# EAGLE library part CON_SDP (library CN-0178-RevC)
SDP Connector
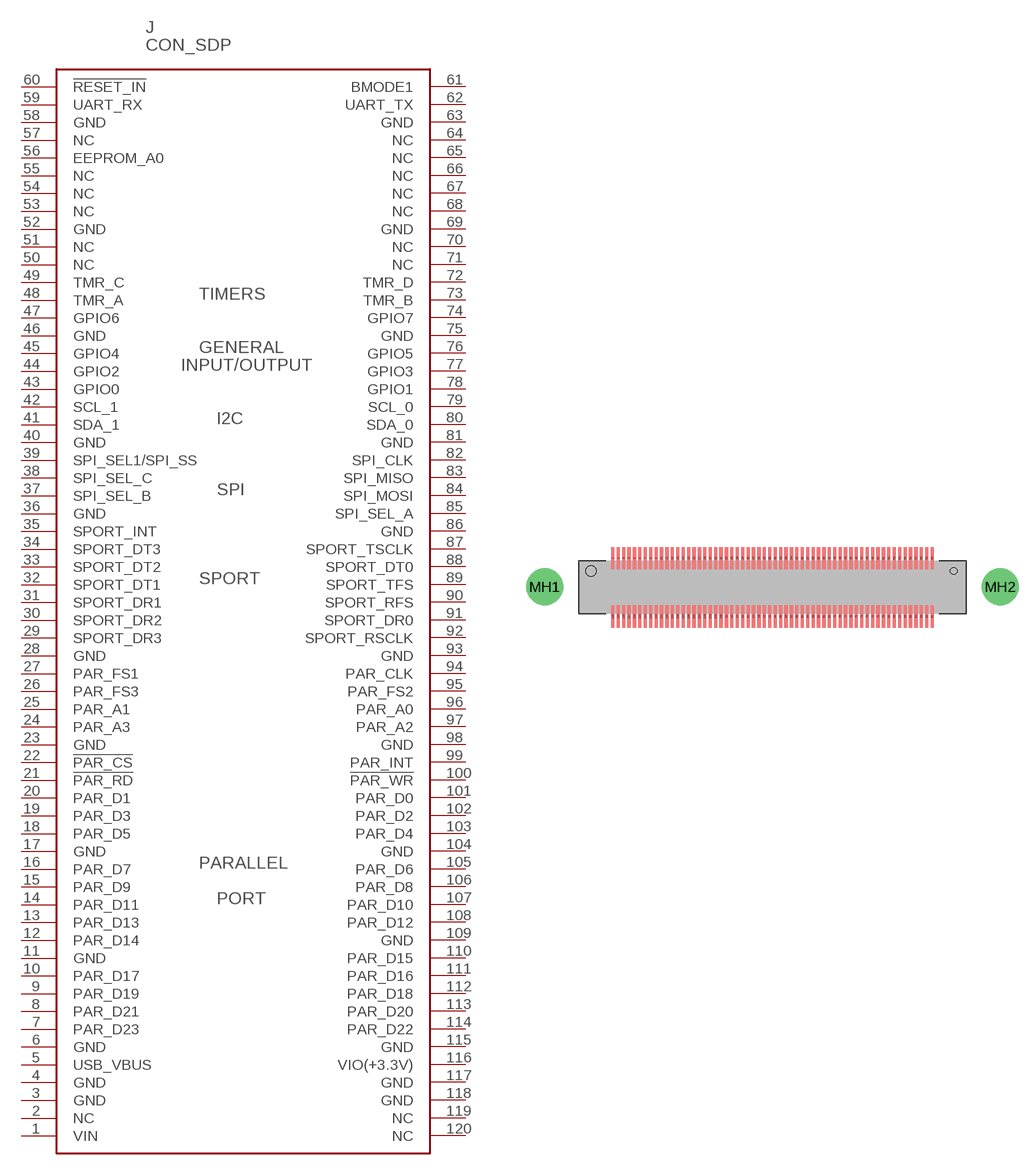
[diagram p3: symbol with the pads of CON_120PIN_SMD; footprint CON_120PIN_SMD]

Designator prefix J

## CON_SDP_120PIN_SMD  [CON_120PIN_SMD]
1  VIN  pas
2  NC  pas
3  GND  pas
4  GND  pas
5  USB_VBUS  pas
6  GND  pas
7  PAR_D23  pas
8  PAR_D21  pas
9  PAR_D19  pas
10  PAR_D17  pas
11  GND  pas
12  PAR_D14  pas
13  PAR_D13  pas
14  PAR_D11  pas
15  PAR_D9  pas
16  PAR_D7  pas
17  GND  pas
18  PAR_D5  pas
19  PAR_D3  pas
20  PAR_D1  pas
21  !PAR_RD  pas
22  !PAR_CS  pas
23  GND  pas
24  PAR_A3  pas
25  PAR_A1  pas
26  PAR_FS3  pas
27  PAR_FS1  pas
28  GND  pas
29  SPORT_DR3  pas
30  SPORT_DR2  pas
31  SPORT_DR1  pas
32  SPORT_DT1  pas
33  SPORT_DT2  pas
34  SPORT_DT3  pas
35  SPORT_INT  pas
36  GND  pas
37  SPI_SEL_B  pas
38  SPI_SEL_C  pas
39  SPI_SEL1/SPI_SS  pas
40  GND  pas
41  SDA_1  pas
42  SCL_1  pas
43  GPIO0  pas
44  GPIO2  pas
45  GPIO4  pas
46  GND  pas
47  GPIO6  pas
48  TMR_A  pas
49  TMR_C  pas
50  NC  pas
51  NC  pas
52  GND  pas
53  NC  pas
54  NC  pas
55  NC  pas
56  EEPROM_A0  pas
57  NC  pas
58  GND  pas
59  UART_RX  pas
60  !RESET_IN  pas
61  BMODE1  pas
62  UART_TX  pas
63  GND  pas
64  NC  pas
65  NC  pas
66  NC  pas
67  NC  pas
68  NC  pas
69  GND  pas
70  NC  pas
71  NC  pas
72  TMR_D  pas
73  TMR_B  pas
74  GPIO7  pas
75  GND  pas
76  GPIO5  pas
77  GPIO3  pas
78  GPIO1  pas
79  SCL_0  pas
80  SDA_0  pas
81  GND  pas
82  SPI_CLK  pas
83  SPI_MISO  pas
84  SPI_MOSI  pas
85  SPI_SEL_A  pas
86  GND  pas
87  SPORT_TSCLK  pas
88  SPORT_DT0  pas
89  SPORT_TFS  pas
90  SPORT_RFS  pas
91  SPORT_DR0  pas
92  SPORT_RSCLK  pas
93  GND  pas
94  PAR_CLK  pas
95  PAR_FS2  pas
96  PAR_A0  pas
97  PAR_A2  pas
98  GND  pas
99  PAR_INT  pas
100  !PAR_WR  pas
101  PAR_D0  pas
102  PAR_D2  pas
103  PAR_D4  pas
104  GND  pas
105  PAR_D6  pas
106  PAR_D8  pas
107  PAR_D10  pas
108  PAR_D12  pas
109  GND  pas
110  PAR_D15  pas
111  PAR_D16  pas
112  PAR_D18  pas
113  PAR_D20  pas
114  PAR_D22  pas
115  GND  pas
116  VIO(+3.3V)  pas
117  GND  pas
118  GND  pas
119  NC  pas
120  NC  pas

## Footprint CON_120PIN_SMD (pad centres in mm)
Hirose FX8-120s-SV(21), 120-pin receptacle, FEC 132-4660
smd 0.35 x 2.46: 1 -17.7,3.23; 2 -17.1,3.23; 3 -16.5,3.23; 4 -15.9,3.23; 5 -15.3,3.23; 6 -14.7,3.23; 7 -14.1,3.23; 8 -13.5,3.23; 9 -12.9,3.23; 10 -12.3,3.23; 11 -11.7,3.23; 12 -11.1,3.23; 13 -10.5,3.23; 14 -9.9,3.23; 15 -9.3,3.23; 16 -8.7,3.23; 17 -8.1,3.23; 18 -7.5,3.23; 19 -6.9,3.23; 20 -6.3,3.23; 21 -5.7,3.23; 22 -5.1,3.23; 23 -4.5,3.23; 24 -3.9,3.23; 25 -3.3,3.23; 26 -2.7,3.23; 27 -2.1,3.23; 28 -1.5,3.23; 29 -0.9,3.23; 30 -0.3,3.23; 31 0.3,3.23; 32 0.9,3.23; 33 1.5,3.23; 34 2.1,3.23; 35 2.7,3.23; 36 3.3,3.23; 37 3.9,3.23; 38 4.5,3.23; 39 5.1,3.23; 40 5.7,3.23; 41 6.3,3.23; 42 6.9,3.23; 43 7.5,3.23; 44 8.1,3.23; 45 8.7,3.23; 46 9.3,3.23; 47 9.9,3.23; 48 10.5,3.23; 49 11.1,3.23; 50 11.7,3.23; 51 12.3,3.23; 52 12.9,3.23; 53 13.5,3.23; 54 14.1,3.23; 55 14.7,3.23; 56 15.3,3.23; 57 15.9,3.23; 58 16.5,3.23; 59 17.1,3.23; 60 17.7,3.23; 61 17.7,-3.23; 62 17.1,-3.23; 63 16.5,-3.23; 64 15.9,-3.23; 65 15.3,-3.23; 66 14.7,-3.23; 67 14.1,-3.23; 68 13.5,-3.23; 69 12.9,-3.23; 70 12.3,-3.23; 71 11.7,-3.23; 72 11.1,-3.23; 73 10.5,-3.23; 74 9.9,-3.23; 75 9.3,-3.23; 76 8.7,-3.23; 77 8.1,-3.23; 78 7.5,-3.23; 79 6.9,-3.23; 80 6.3,-3.23; 81 5.7,-3.23; 82 5.1,-3.23; 83 4.5,-3.23; 84 3.9,-3.23; 85 3.3,-3.23; 86 2.7,-3.23; 87 2.1,-3.23; 88 1.5,-3.23; 89 0.9,-3.23; 90 0.3,-3.23; 91 -0.3,-3.23; 92 -0.9,-3.23; 93 -1.5,-3.23; 94 -2.1,-3.23; 95 -2.7,-3.23; 96 -3.3,-3.23; 97 -3.9,-3.23; 98 -4.5,-3.23; 99 -5.1,-3.23; 100 -5.7,-3.23; 101 -6.3,-3.23; 102 -6.9,-3.23; 103 -7.5,-3.23; 104 -8.1,-3.23; 105 -8.7,-3.23; 106 -9.3,-3.23; 107 -9.9,-3.23; 108 -10.5,-3.23; 109 -11.1,-3.23; 110 -11.7,-3.23; 111 -12.3,-3.23; 112 -12.9,-3.23; 113 -13.5,-3.23; 114 -14.1,-3.23; 115 -14.7,-3.23; 116 -15.3,-3.23; 117 -15.9,-3.23; 118 -16.5,-3.23; 119 -17.1,-3.23; 120 -17.7,-3.23
drill 3.124 round: MH1 -25.25,0.05; MH2 25.25,0.05
hole 0.762 at 20.1,1.8
hole 1.168 at -20.1,1.8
